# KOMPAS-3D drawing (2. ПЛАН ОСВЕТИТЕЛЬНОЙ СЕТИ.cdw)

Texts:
  ДП.11.213.03.000.00.ЭО
  Телятник на 120 голов в СПК колхоз "Дзержинского" Даниловского МР Ярославской обл.
  НСП21 1 х 40 2,5
  ЯОУ-8501
  ВВГ (3 х 1,5)
  ВВГ (3 х 2,5)
  УСЛОВНЫЕ ОБОЗНАЧЕНИЯ
  - ящик осветительный марки ЯОУ - 8501, рассчитанный
  на 6 отходящих групп освещения.
  - светильник рабочего освещения типа ЛСП 21 - общего
  назначения, подвесной, с двумя люминесцентными лампами
  типа ЛБ - 40, для промышленных зданий, 21 серии.
  - светильник дежурного освещения типа ЛСП 21 - общего
  - светильник рабочего освещения типа НСП 21 - общего
  назначения, подвесной, лампами накаливания, с одной или
  двумя лампами типа Б215-225 различной мощности, для
  промышленных зданий, 21 серии.
  - кабель трёхжильный марки ВВГ, с медными жилами, в
  поливинилхлоридной изоляции, предназначенный для
  питания сети рабочего освещения.
  питания сети дежурного освещения.
  № поз.
  Наименование помещения
  Площадь,
  Стойловое
  Веткабинет
  Инвентарная
  Венткамера
  Электрощитовая
  Служебная
  Санузел
  Кладовая дезосредств
  Фуражная
  Помещение для приготовления ЗЦМ
  Помещение для погрузки навоза в ТС
  Коридор
  ЭКСПЛИКАЦИЯ ПОМЕЩЕНИЙ
  Нормированная
  освещённость, лк
  - настенный выключатель открытой установки,
  однополюсной.
  СХЕМА ОСВЕТИТЕЛЬНОЙ СЕТИ
  Источник питания;
  устройство ввода
  Распределительное
  устройство;
  групповой щит;
  защитная аппаратура
  Марка, сечение кабеля;
  устройства защиты
  по группам
  Нагрузка на
  группу
  Наименование;
  количество
  ПР85-067
  ввод в здание
  ВВГ (4 х 10)
  ВА51-31
  ВВГ(5х1,5)
  ВВГ(3х1,5)
  ВВГ(3х2,5)
  АЕ1031
  ЛСП21-2х40; 4
  ЛСП21-2х40; 14
  НСП21-1х40; 7
  НСП21-1х150; 2
  НСП21-2х200; 2
  НСП21-1х100; 2
  НСП21-1х60;  4
  НСП21-2х150; 6
  НСП21-1х150; 6
  НСП21-1х100; 4
  заливка
  Куракин.
  ФГОУ ВПО ЯГСХА
  Телятник на 120 голов
  в СПК колхоз "Дзержинского"
  Даниловского МР Ярославской обл.
  Шмигель
  План осветительной сети.
  ДП08Ф040200009Э0-
  Королёва
  Орлов
Dimensions and other numbers on the sheet: 2; 3; 6; 4; 7; 8; 9; 10; 11; 1; 12; 12000; 42000; 30000; 6000; 4500; 2 НСП21 1 х 150 2,5; 2 НСП21 1 х 100 1,7; 4 НСП21 2 х 150 2,5; 4 НСП21 1 х 60 1,7; 2 НСП21 1 х 100 2,5; 2 НСП21 2 х 200 1,7; 20 лк; 100 лк; 75 лк; 5 лк; 2 НСП21 2 х 150 1,7; 18 ЛСП21 2 х 40 3,2; 1 группа,  Р = 320 Вт; 2 группа,  Р = 1120 Вт; 3 группа,  Р = 580 Вт; 6 группа,  Р = 1300 Вт; 5 группа,  Р = 1800 Вт; 4 группа,  Р = 1240 Вт; 2 НСП21; 6 НСП21; 5; 504; 16,6; 15,7; 29,5; 11,0; 25,0; 3,8; 12,2; 14,7; 27,5; 22,4; 30,1; 75; 100; 20; 12,5; 25; 6,3; 1:100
